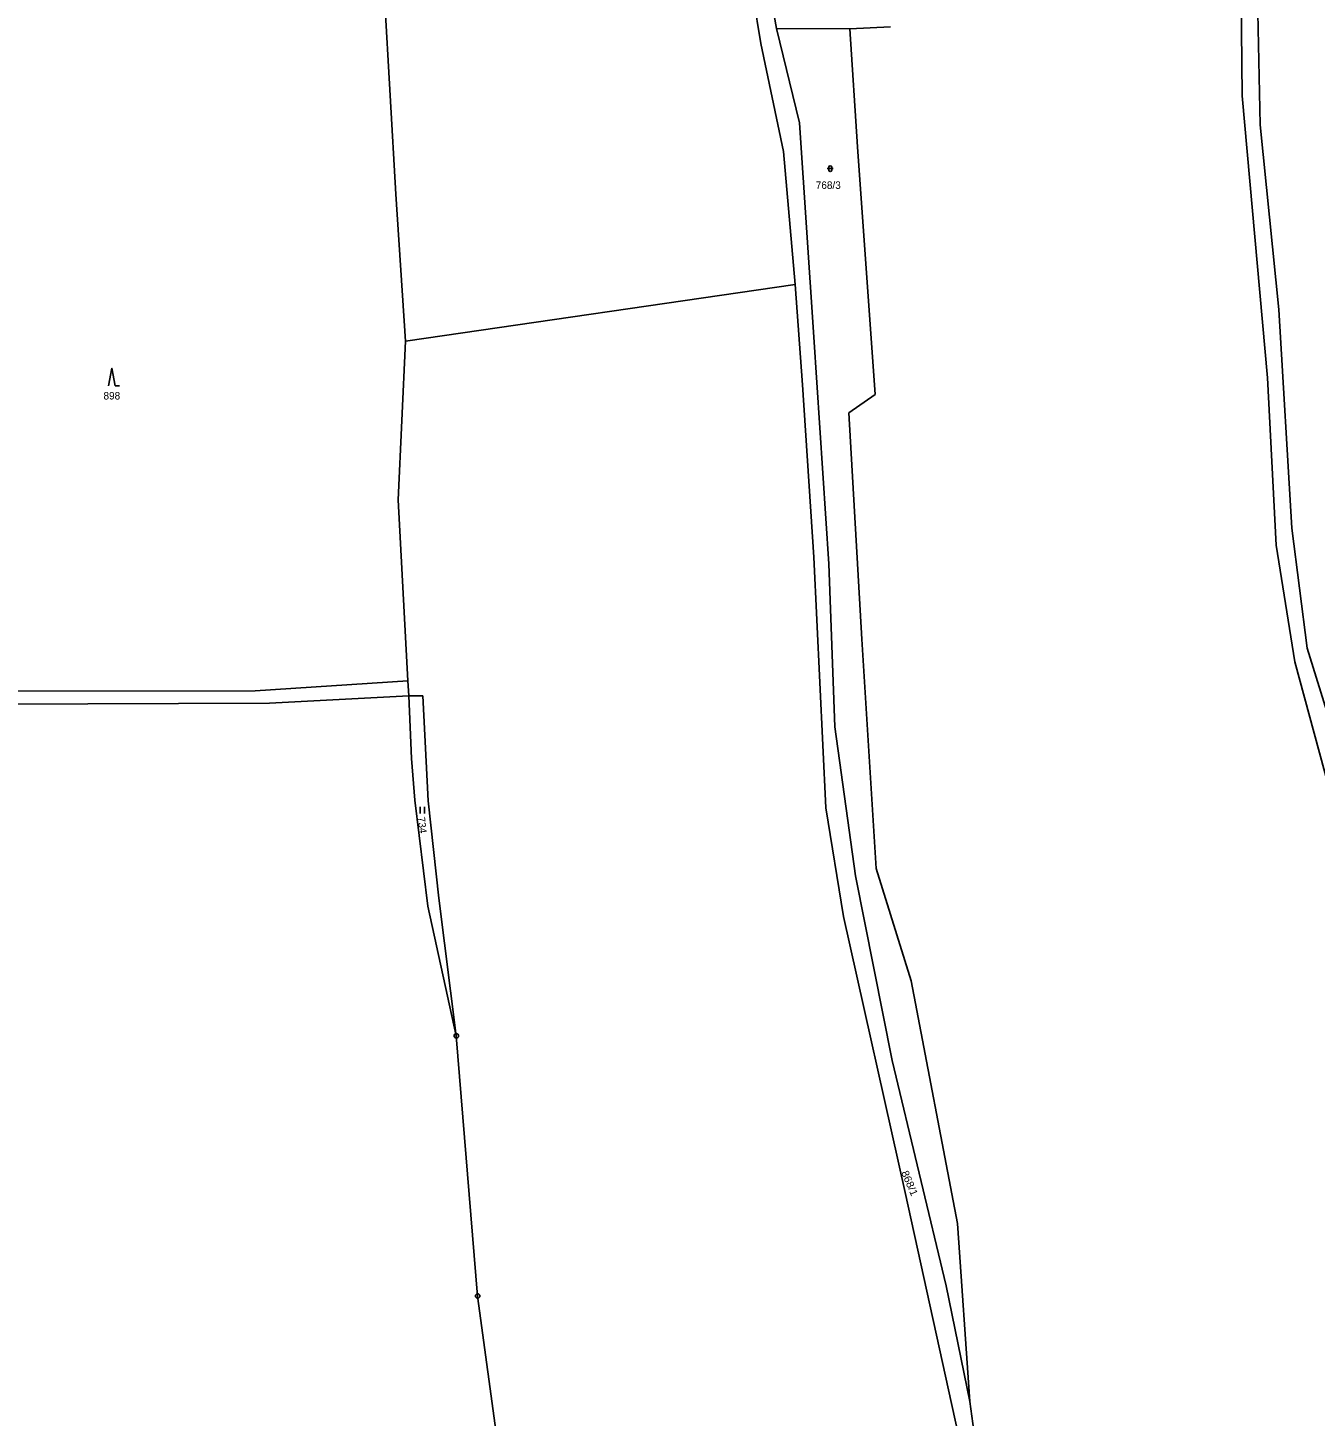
# Model space of a CAD drawing. Extents: x -739410 to -735662, y -942282 to -940043.
# Drawn here: x -738091.3 to -737798.5, y -940936.4 to -940620.7 of the extents above; entities that cross this region are included whole.
import ezdxf
from ezdxf.enums import TextEntityAlignment as Align

# ---------------------------------------------------------------- set-up
doc = ezdxf.new("R2010")
doc.units = 0
doc.header["$LTSCALE"] = 0.68
for name, color, linetype, lineweight in [('1', 7, 'Continuous', 25), ('3', 7, 'Continuous', 25), ('8', 7, 'Continuous', 25)]:
    doc.layers.add(name, color=color, linetype=linetype, lineweight=lineweight)
doc.layers.add('2', color=7, linetype='Continuous')

msp = doc.modelspace()

# ---------------------------------------------------------------- linework, layer by layer
at = {"layer": '1'}
for p, q in [((-737930.94, -940585.95), (-737924.62, -940624.25)), ((-737921.07, -940620.9), (-737927.26, -940585.88)), ((-737815.18, -940636.19), (-737815.58, -940597.21)), ((-737811.98, -940597.17), (-737811.05, -940642.82)), ((-738007.61, -940658.52), (-738010.34, -940610)), ((-737921.07, -940620.9), (-737915.84, -940642.36)), ((-737904.34, -940620.97), (-737921.07, -940620.9)), ((-737895.09, -940620.52), (-737904.34, -940620.97)), ((-737904.34, -940620.97), (-737902.65, -940647.79)), ((-737924.62, -940624.25), (-737919.47, -940648.83)), ((-737809.38, -940700.35), (-737815.18, -940636.19)), ((-737915.84, -940642.36), (-737912.51, -940691.09)), ((-737811.05, -940642.82), (-737806.8, -940684.79)), ((-737919.47, -940648.83), (-737916.76, -940679.1)), ((-737902.65, -940647.79), (-737898.61, -940704.1)), ((-738005.39, -940692.01), (-738007.61, -940658.52)), ((-738005.39, -940692.01), (-737916.76, -940679.1)), ((-737916.76, -940679.1), (-737915.09, -940701.88)), ((-737806.8, -940684.79), (-737803.84, -940734.52)), ((-737912.51, -940691.09), (-737909.16, -940742.61)), ((-738007.07, -940728.05), (-738005.39, -940692.01)), ((-737807.45, -940738.38), (-737809.38, -940700.35)), ((-737915.09, -940701.88), (-737912.51, -940741.06)), ((-737898.61, -940704.1), (-737904.59, -940708.27)), ((-737904.59, -940708.27), (-737901.66, -940759.72)), ((-738004.87, -940769.21), (-738007.07, -940728.05)), ((-737803.84, -940734.52), (-737800.36, -940761.82)), ((-737803.19, -940764.9), (-737807.45, -940738.38)), ((-737909.8, -940798.11), (-737912.51, -940741.06)), ((-737909.16, -940742.61), (-737907.74, -940779.65)), ((-737901.66, -940759.72), (-737898.39, -940811.88)), ((-737800.36, -940761.82), (-737795.25, -940778.4)), ((-737793.2, -940801.8), (-737803.19, -940764.9)), ((-738039.58, -940771.51), (-738004.87, -940769.21)), ((-738004.64, -940772.65), (-738004.87, -940769.21)), ((-738100.35, -940771.59), (-738039.58, -940771.51)), ((-738036.32, -940774.29), (-738004.64, -940772.65)), ((-738004.64, -940772.65), (-738001.49, -940772.65)), ((-738004.64, -940772.65), (-738004.04, -940786.88)), ((-738001.49, -940772.65), (-738000.23, -940796.54)), ((-738100.3, -940774.55), (-738036.32, -940774.29)), ((-737907.74, -940779.65), (-737903.1, -940813.57)), ((-738004.04, -940786.88), (-738003.25, -940796.35)), ((-738003.25, -940796.35), (-738000.32, -940820.47)), ((-738000.23, -940796.54), (-737997.84, -940818.6)), ((-737905.8, -940822.81), (-737909.8, -940798.11)), ((-737903.1, -940813.57), (-737894.72, -940855.55)), ((-737898.39, -940811.88), (-737890.38, -940837.43)), ((-738000.32, -940820.47), (-737993.84, -940849.95)), ((-737997.84, -940818.6), (-737993.84, -940849.95)), ((-737891.75, -940885.54), (-737905.8, -940822.81)), ((-737890.38, -940837.43), (-737879.9, -940892.63)), ((-737988.99, -940909.11), (-737993.84, -940849.95)), ((-737894.72, -940855.55), (-737882.47, -940906.83)), ((-737878.99, -940943.6), (-737891.75, -940885.54)), ((-737879.9, -940892.63), (-737877.06, -940933.1)), ((-737983.15, -940951.96), (-737988.99, -940909.11)), ((-737882.47, -940906.83), (-737877.06, -940933.1)), ((-737877.06, -940933.1), (-737876.16, -940939.79))]:
    msp.add_line(p, q, dxfattribs=at)
at = {"layer": '3'}
for p, q in [((-737909.491, -940652.741), (-737908.149, -940652.741)), ((-737909.155, -940652.405), (-737909.155, -940653.076)), ((-737908.485, -940653.076), (-737908.485, -940652.405)), ((-738071.42, -940702.12), (-738070.424, -940702.12)), ((-738002.081, -940799.36), (-738002.081, -940797.86)), ((-738001.08, -940799.36), (-738001.08, -940797.86))]:
    msp.add_line(p, q, dxfattribs=at)
msp.add_lwpolyline([(-738071.42, -940702.12), (-738072.17, -940698.12), (-738072.92, -940702.12)], dxfattribs=at)
for centre, start, end in [((-737908.82, -940652.4056), 0, 180), ((-737908.82, -940653.0756), 180, 359.98789)]:
    msp.add_arc(centre, 0.335, start, end, dxfattribs=at)
at = {"layer": '8'}
for centre, radius in [((-737993.84, -940849.9499), 0.5), ((-737993.84, -940849.9499), 0.0303), ((-737988.99, -940909.1099), 0.5), ((-737988.99, -940909.1099), 0.0303)]:
    msp.add_circle(centre, radius, dxfattribs=at)

# ---------------------------------------------------------------- texts
at = {"layer": '2'}
for s, p in [('768/3', (-737909.26, -940657.345)), ('898', (-738072.169, -940705.245))]:
    msp.add_text(s, height=1.7, dxfattribs=at).set_placement(p, align=Align.CENTER)
msp.add_text('734', height=1.7, rotation=277, dxfattribs=at).set_placement((-738002.435, -940802.1039), align=Align.CENTER)
at = {"layer": '2', "width": 1.05}
msp.add_text('868/1', height=1.7, rotation=293, dxfattribs=at).set_placement((-737891.529, -940883.7849), align=Align.CENTER)

doc.saveas('drawing.dxf')
